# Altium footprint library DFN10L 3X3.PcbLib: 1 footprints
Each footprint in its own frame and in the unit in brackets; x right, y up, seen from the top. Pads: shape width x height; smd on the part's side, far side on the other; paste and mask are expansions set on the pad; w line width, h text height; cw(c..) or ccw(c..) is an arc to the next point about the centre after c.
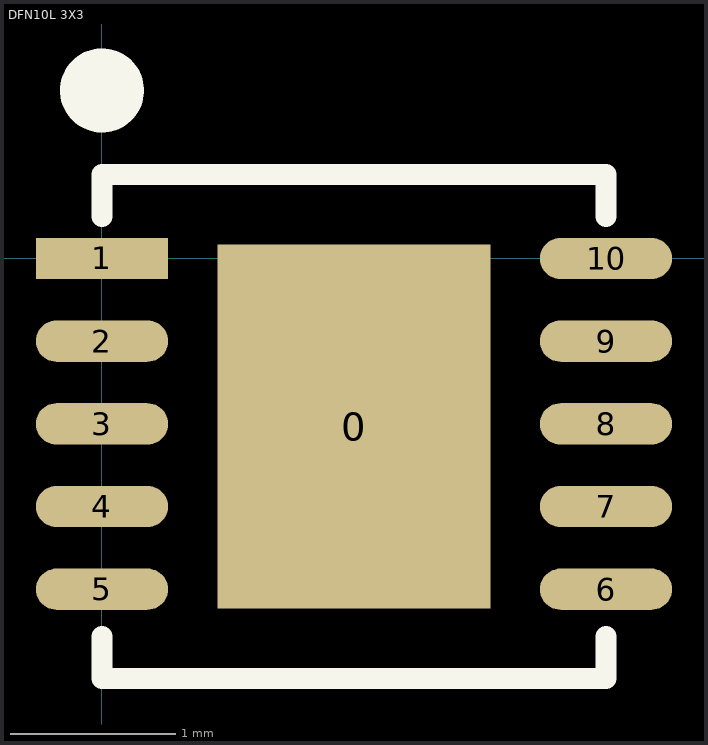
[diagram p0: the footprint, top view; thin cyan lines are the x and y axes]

## DFN10L 3X3 [mm]
pads (11):
  rect 1.65x2.2 smd: 0(1.524,-1.016)
  rect 0.8x0.25 smd: 1(0,0)
  oval 0.8x0.25 smd: 2(0,-0.5) 3(0,-1) 4(0,-1.5) 5(0,-2) 6(3.048,-2) 7(3.048,-1.5) 8(3.048,-1) 9(3.048,-0.5) 10(3.048,0)
Top Overlay:
  circle w0.254: c0,1.016 r0.127
  lines w0.127: 0,-2.286 0,-2.54 3.048,-2.54 3.048,-2.286 ; 0,0.254 0,0.508 3.048,0.508 3.048,0.254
